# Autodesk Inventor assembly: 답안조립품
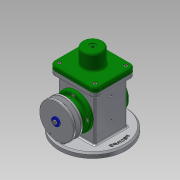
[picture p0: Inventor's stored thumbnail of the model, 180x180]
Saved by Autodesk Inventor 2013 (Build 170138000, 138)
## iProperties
Created: 2019-08
Part Number: 답안조립품
Document SubType Name: Assembly
Designer: Administrator
Author: Administrator
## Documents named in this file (18)
- C:\Users\Administrator\Desktop\490804V1005\답안조립품.iam
- C:\Users\Administrator\Desktop\490804V1005\본체.ipt
- C:\Users\Administrator\Desktop\490804V1005\E-링.ipt
- C:\Users\Administrator\Desktop\490804V1005\V-벨트풀리.ipt
- C:\Users\Administrator\Desktop\490804V1005\덮개.ipt
- C:\Users\Administrator\Desktop\490804V1005\뒤커버.ipt
- C:\Users\Administrator\Desktop\490804V1005\링크.ipt
- C:\Users\Administrator\Desktop\490804V1005\베어링 17 x 40 x 12.ipt
- C:\Users\Administrator\Desktop\490804V1005\볼트 M4 x 8.ipt
- C:\Users\Administrator\Desktop\490804V1005\볼트 M4 x 10.ipt
- C:\Users\Administrator\Desktop\490804V1005\슬라이더.ipt
- C:\Users\Administrator\Desktop\490804V1005\앞커버.ipt
- C:\Users\Administrator\Desktop\490804V1005\오일 실 17 30 8.ipt
- C:\Users\Administrator\Desktop\490804V1005\와셔 4x16.ipt
- C:\Users\Administrator\Desktop\490804V1005\클레비스 핀 6 x 22.ipt
- 클레비스 핀 6 x 22.ipt
- C:\Users\Administrator\Desktop\490804V1005\키 4 x 4 x 12.ipt
- C:\Users\Administrator\Desktop\490804V1005\편심축.ipt
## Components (2 placed, 2 different names)
1. E-링:1
2. V-벨트풀리:1
